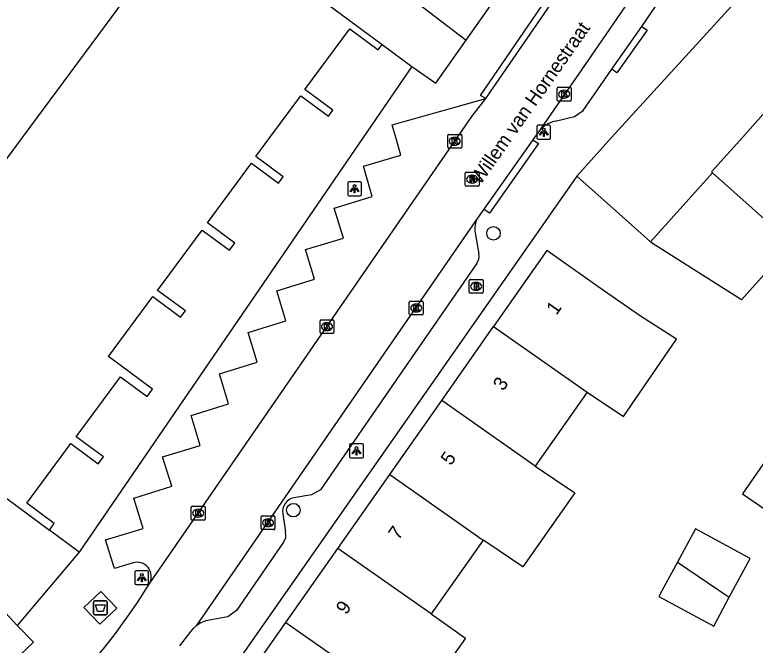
# Model space of a CAD drawing. Extents: x 161801 to 162379, y 382315 to 382832.
# Drawn here: x 161941.1 to 161994.6, y 382713.3 to 382758.9 of the extents above; entities that cross this region are included whole.
import ezdxf

# ---------------------------------------------------------------- set-up
doc = ezdxf.new("R2010")
doc.units = 0
for name, color, linetype in [('IMGEO_Afval_apart_plaats', 7, 'Continuous'), ('IMGEO_Boom', 7, 'Continuous'), ('IMGEO_Brandkraan', 7, 'Continuous'), ('IMGEO_Kolk', 7, 'Continuous'), ('IMGEO_Lichtpunt', 7, 'Continuous'), ('IMGEO_Openbare_ruimte_label', 7, 'Continuous'), ('IMGEO_Pand', 7, 'Continuous'), ('IMGEO_Pand_nummerreeks', 7, 'Continuous'), ('IMGEO_Parkeervlak_open', 7, 'Continuous'), ('IMGEO_Rijbaan_lokaal_open', 7, 'Continuous'), ('IMGEO_Rioolput', 7, 'Continuous'), ('IMGEO_Voetpad_gesloten', 7, 'Continuous'), ('IMGEO_Voetpad_open', 7, 'Continuous')]:
    doc.layers.add(name, color=color, linetype=linetype)

msp = doc.modelspace()

# ---------------------------------------------------------------- linework, layer by layer
at = {"layer": 'IMGEO_Afval_apart_plaats'}
for p, q in [((161946.804, 382715.605), (161946.804, 382716.405)), ((161946.804, 382716.405), (161946.804, 382715.605)), ((161946.904, 382716.505), (161947.694, 382716.505)), ((161947.694, 382716.505), (161946.904, 382716.505)), ((161947.794, 382716.405), (161947.794, 382715.605)), ((161947.794, 382715.605), (161947.794, 382716.405)), ((161947.694, 382715.505), (161946.904, 382715.505)), ((161946.904, 382715.505), (161947.694, 382715.505))]:
    msp.add_line(p, q, dxfattribs=at)
msp.add_lwpolyline([(161946.947, 382716.219), (161947.651, 382716.219), (161947.502, 382715.749), (161947.096, 382715.749), (161946.947, 382716.219)], dxfattribs=at)
for centre, start, end in [((161946.904, 382716.405), 90, 180), ((161946.904, 382716.405), 90, 180), ((161947.694, 382716.405), 0, 90), ((161947.694, 382716.405), 360, 90), ((161946.904, 382715.605), 180, 270), ((161946.904, 382715.605), 180, 270), ((161947.694, 382715.605), 270, 0), ((161947.694, 382715.605), 270, 0)]:
    msp.add_arc(centre, 0.1, start, end, dxfattribs=at)
at = {"layer": 'IMGEO_Boom'}
for centre in [(161975.717, 382743.07), (161961.254, 382723.06)]:
    msp.add_circle(centre, 0.489, dxfattribs=at)
at = {"layer": 'IMGEO_Brandkraan'}
for p, q in [((161973.966, 382738.812), (161973.966, 382739.664)), ((161974.041, 382739.738), (161974.893, 382739.738)), ((161974.454, 382739.518), (161974.479, 382739.518)), ((161974.967, 382739.664), (161974.967, 382738.812)), ((161974.477, 382738.958), (161974.452, 382738.958)), ((161974.893, 382738.738), (161974.041, 382738.738))]:
    msp.add_line(p, q, dxfattribs=at)
for points in [[(161973.966, 382738.812), (161973.966, 382739.664)], [(161974.041, 382739.738), (161974.893, 382739.738)], [(161974.314, 382739.438), (161974.314, 382739.038), (161974.527, 382739.038)], [(161974.545, 382739.438), (161974.314, 382739.438)], [(161974.493, 382739.357), (161974.439, 382739.357), (161974.439, 382739.281)], [(161974.967, 382739.664), (161974.967, 382738.812)], [(161974.439, 382739.281), (161974.492, 382739.281)], [(161974.501, 382739.205), (161974.439, 382739.205), (161974.439, 382739.124)], [(161974.439, 382739.124), (161974.501, 382739.124)], [(161974.893, 382738.738), (161974.041, 382738.738)]]:
    msp.add_lwpolyline(points, dxfattribs=at)
for centre, radius, start, end in [((161974.043, 382739.662), 0.0765, 91.552, 178.448), ((161974.043, 382739.662), 0.0765, 91.552, 178.448), ((161974.494, 382739.319), 0.0379, 267.8285, 90.9355), ((161974.549, 382739.293), 0.145, 59.4692, 91.5367), ((161974.574, 382739.34), 0.0922, 285.5137, 58.1501), ((161974.891, 382739.662), 0.0765, 1.552, 88.448), ((161974.891, 382739.662), 0.0765, 1.552, 88.448), ((161974.043, 382738.814), 0.0765, 181.552, 268.448), ((161974.043, 382738.814), 0.0765, 181.552, 268.448), ((161974.502, 382739.164), 0.0404, 269.8759, 90.5077), ((161974.533, 382739.289), 0.251, 268.6676, 293.5347), ((161974.579, 382739.148), 0.105, 301.3115, 78.989), ((161974.891, 382738.814), 0.0765, 271.552, 358.448), ((161974.891, 382738.814), 0.0765, 271.552, 358.448)]:
    msp.add_arc(centre, radius, start, end, dxfattribs=at)
for centre, major_axis, ratio, start_param, end_param in [((161974.453, 382739.238), (-0.387, 0.002), 0.722429, 4.712389, 7.853982), ((161974.478, 382739.238), (-0.39, 0.002), 0.717154, 1.570796, 4.712389)]:
    msp.add_ellipse(centre, major_axis=major_axis, ratio=ratio, start_param=start_param, end_param=end_param, dxfattribs=at)
at = {"layer": 'IMGEO_Kolk'}
for p, q in [((161980.328, 382752.702), (161980.328, 382753.554)), ((161980.403, 382753.628), (161981.255, 382753.628)), ((161980.816, 382753.408), (161980.841, 382753.408)), ((161981.329, 382753.554), (161981.329, 382752.702)), ((161980.839, 382752.848), (161980.814, 382752.848)), ((161981.255, 382752.628), (161980.403, 382752.628)), ((161972.421, 382749.297), (161972.421, 382750.149)), ((161972.496, 382750.223), (161973.348, 382750.223)), ((161973.422, 382750.149), (161973.422, 382749.297)), ((161972.909, 382750.003), (161972.934, 382750.003)), ((161973.348, 382749.223), (161972.496, 382749.223)), ((161972.932, 382749.443), (161972.907, 382749.443)), ((161969.634, 382737.246), (161969.634, 382738.098)), ((161969.709, 382738.172), (161970.561, 382738.172)), ((161970.122, 382737.952), (161970.147, 382737.952)), ((161970.635, 382738.098), (161970.635, 382737.246)), ((161970.145, 382737.392), (161970.12, 382737.392)), ((161963.184, 382735.901), (161963.184, 382736.753)), ((161963.259, 382736.827), (161964.111, 382736.827)), ((161964.185, 382736.753), (161964.185, 382735.901)), ((161970.561, 382737.172), (161969.709, 382737.172)), ((161963.672, 382736.607), (161963.697, 382736.607)), ((161964.111, 382735.827), (161963.259, 382735.827)), ((161963.695, 382736.047), (161963.67, 382736.047)), ((161953.948, 382723.346), (161954.8, 382723.346)), ((161953.873, 382722.42), (161953.873, 382723.272)), ((161954.361, 382723.126), (161954.386, 382723.126)), ((161954.874, 382723.272), (161954.874, 382722.42)), ((161954.8, 382722.346), (161953.948, 382722.346)), ((161954.384, 382722.566), (161954.359, 382722.566)), ((161958.924, 382721.728), (161958.924, 382722.58)), ((161958.999, 382722.654), (161959.851, 382722.654)), ((161959.412, 382722.434), (161959.437, 382722.434)), ((161959.925, 382722.58), (161959.925, 382721.728)), ((161959.435, 382721.874), (161959.41, 382721.874)), ((161959.851, 382721.654), (161958.999, 382721.654))]:
    msp.add_line(p, q, dxfattribs=at)
for points in [[(161980.328, 382752.702), (161980.328, 382753.554)], [(161980.403, 382753.628), (161981.255, 382753.628)], [(161980.649, 382753.328), (161980.772, 382753.328), (161980.772, 382753.177), (161980.902, 382753.328), (161981.066, 382753.328), (161980.92, 382753.177), (161981.073, 382752.928), (161980.921, 382752.928), (161980.836, 382753.092), (161980.772, 382753.025), (161980.772, 382752.928), (161980.649, 382752.928), (161980.649, 382753.328)], [(161981.329, 382753.554), (161981.329, 382752.702)], [(161981.255, 382752.628), (161980.403, 382752.628)], [(161972.421, 382749.297), (161972.421, 382750.149)], [(161972.496, 382750.223), (161973.348, 382750.223)], [(161973.422, 382750.149), (161973.422, 382749.297)], [(161972.742, 382749.923), (161972.865, 382749.923), (161972.865, 382749.772), (161972.995, 382749.923), (161973.159, 382749.923), (161973.013, 382749.772), (161973.166, 382749.523), (161973.014, 382749.523), (161972.929, 382749.687), (161972.865, 382749.62), (161972.865, 382749.523), (161972.742, 382749.523), (161972.742, 382749.923)], [(161973.348, 382749.223), (161972.496, 382749.223)], [(161969.634, 382737.246), (161969.634, 382738.098)], [(161969.709, 382738.172), (161970.561, 382738.172)], [(161969.955, 382737.872), (161970.078, 382737.872), (161970.078, 382737.721), (161970.208, 382737.872), (161970.372, 382737.872), (161970.226, 382737.721), (161970.379, 382737.472), (161970.227, 382737.472), (161970.142, 382737.636), (161970.078, 382737.569), (161970.078, 382737.472), (161969.955, 382737.472), (161969.955, 382737.872)], [(161970.635, 382738.098), (161970.635, 382737.246)], [(161963.184, 382735.901), (161963.184, 382736.753)], [(161963.259, 382736.827), (161964.111, 382736.827)], [(161964.185, 382736.753), (161964.185, 382735.901)], [(161970.561, 382737.172), (161969.709, 382737.172)], [(161963.505, 382736.527), (161963.628, 382736.527), (161963.628, 382736.376), (161963.758, 382736.527), (161963.922, 382736.527), (161963.776, 382736.376), (161963.929, 382736.127), (161963.777, 382736.127), (161963.692, 382736.291), (161963.628, 382736.224), (161963.628, 382736.127), (161963.505, 382736.127), (161963.505, 382736.527)], [(161964.111, 382735.827), (161963.259, 382735.827)], [(161953.948, 382723.346), (161954.8, 382723.346)], [(161953.873, 382722.42), (161953.873, 382723.272)], [(161954.194, 382723.046), (161954.317, 382723.046), (161954.317, 382722.895), (161954.447, 382723.046), (161954.611, 382723.046), (161954.465, 382722.895), (161954.618, 382722.646), (161954.466, 382722.646), (161954.381, 382722.81), (161954.317, 382722.743), (161954.317, 382722.646), (161954.194, 382722.646), (161954.194, 382723.046)], [(161954.874, 382723.272), (161954.874, 382722.42)], [(161954.8, 382722.346), (161953.948, 382722.346)], [(161958.924, 382721.728), (161958.924, 382722.58)], [(161958.999, 382722.654), (161959.851, 382722.654)], [(161959.245, 382722.354), (161959.368, 382722.354), (161959.368, 382722.203), (161959.498, 382722.354), (161959.662, 382722.354), (161959.516, 382722.203), (161959.669, 382721.954), (161959.517, 382721.954), (161959.432, 382722.118), (161959.368, 382722.051), (161959.368, 382721.954), (161959.245, 382721.954), (161959.245, 382722.354)], [(161959.925, 382722.58), (161959.925, 382721.728)], [(161959.851, 382721.654), (161958.999, 382721.654)]]:
    msp.add_lwpolyline(points, dxfattribs=at)
for centre, start, end in [((161980.405, 382753.552), 91.552, 178.448), ((161980.405, 382753.552), 91.552, 178.448), ((161981.253, 382753.552), 1.552, 88.448), ((161981.253, 382753.552), 1.552, 88.448), ((161980.405, 382752.704), 181.552, 268.448), ((161980.405, 382752.704), 181.552, 268.448), ((161981.253, 382752.704), 271.552, 358.448), ((161981.253, 382752.704), 271.552, 358.448), ((161972.498, 382750.147), 91.552, 178.448), ((161972.498, 382750.147), 91.552, 178.448), ((161973.346, 382750.147), 1.552, 88.448), ((161973.346, 382750.147), 1.552, 88.448), ((161972.498, 382749.299), 181.552, 268.448), ((161972.498, 382749.299), 181.552, 268.448), ((161973.346, 382749.299), 271.552, 358.448), ((161973.346, 382749.299), 271.552, 358.448), ((161969.711, 382738.096), 91.552, 178.448), ((161969.711, 382738.096), 91.552, 178.448), ((161970.559, 382738.096), 1.552, 88.448), ((161970.559, 382738.096), 1.552, 88.448), ((161969.711, 382737.248), 181.552, 268.448), ((161969.711, 382737.248), 181.552, 268.448), ((161970.559, 382737.248), 271.552, 358.448), ((161970.559, 382737.248), 271.552, 358.448), ((161963.261, 382736.751), 91.552, 178.448), ((161963.261, 382736.751), 91.552, 178.448), ((161964.109, 382736.751), 1.552, 88.448), ((161964.109, 382736.751), 1.552, 88.448), ((161963.261, 382735.903), 181.552, 268.448), ((161963.261, 382735.903), 181.552, 268.448), ((161964.109, 382735.903), 271.552, 358.448), ((161964.109, 382735.903), 271.552, 358.448), ((161953.95, 382723.27), 91.552, 178.448), ((161953.95, 382723.27), 91.552, 178.448), ((161954.798, 382723.27), 1.552, 88.448), ((161954.798, 382723.27), 1.552, 88.448), ((161953.95, 382722.422), 181.552, 268.448), ((161953.95, 382722.422), 181.552, 268.448), ((161954.798, 382722.422), 271.552, 358.448), ((161954.798, 382722.422), 271.552, 358.448), ((161959.001, 382722.578), 91.552, 178.448), ((161959.001, 382722.578), 91.552, 178.448), ((161959.849, 382722.578), 1.552, 88.448), ((161959.849, 382722.578), 1.552, 88.448), ((161959.001, 382721.73), 181.552, 268.448), ((161959.001, 382721.73), 181.552, 268.448), ((161959.849, 382721.73), 271.552, 358.448), ((161959.849, 382721.73), 271.552, 358.448)]:
    msp.add_arc(centre, 0.0765, start, end, dxfattribs=at)
for centre, major_axis, ratio, start_param, end_param in [((161980.815, 382753.128), (-0.387, 0.002), 0.722429, 4.712389, 7.853982), ((161980.84, 382753.128), (-0.39, 0.002), 0.717154, 1.570796, 4.712389), ((161972.908, 382749.723), (-0.387, 0.002), 0.722429, 4.712389, 7.853982), ((161972.933, 382749.723), (-0.39, 0.002), 0.717154, 1.570796, 4.712389), ((161970.121, 382737.672), (-0.387, 0.002), 0.722429, 4.712389, 7.853982), ((161970.146, 382737.672), (-0.39, 0.002), 0.717154, 1.570796, 4.712389), ((161963.671, 382736.327), (-0.387, 0.002), 0.722429, 4.712389, 7.853982), ((161963.696, 382736.327), (-0.39, 0.002), 0.717154, 1.570796, 4.712389), ((161954.36, 382722.846), (-0.387, 0.002), 0.722429, 4.712389, 7.853982), ((161954.385, 382722.846), (-0.39, 0.002), 0.717154, 1.570796, 4.712389), ((161959.411, 382722.154), (-0.387, 0.002), 0.722429, 4.712389, 7.853982), ((161959.436, 382722.154), (-0.39, 0.002), 0.717154, 1.570796, 4.712389)]:
    msp.add_ellipse(centre, major_axis=major_axis, ratio=ratio, start_param=start_param, end_param=end_param, dxfattribs=at)
at = {"layer": 'IMGEO_Lichtpunt'}
for p, q in [((161978.856, 382750.781), (161978.856, 382749.974)), ((161978.856, 382750.781), (161978.856, 382749.974)), ((161979.758, 382750.876), (161978.95, 382750.876)), ((161979.758, 382750.876), (161978.95, 382750.876)), ((161979.852, 382749.974), (161979.852, 382750.781)), ((161979.852, 382749.974), (161979.852, 382750.781)), ((161978.95, 382749.88), (161979.758, 382749.88)), ((161978.95, 382749.88), (161979.758, 382749.88)), ((161965.183, 382746.692), (161965.183, 382745.885)), ((161965.183, 382746.692), (161965.183, 382745.885)), ((161966.085, 382746.787), (161965.277, 382746.787)), ((161966.085, 382746.787), (161965.277, 382746.787)), ((161966.179, 382745.885), (161966.179, 382746.692)), ((161966.179, 382745.885), (161966.179, 382746.692)), ((161965.277, 382745.791), (161966.085, 382745.791)), ((161965.277, 382745.791), (161966.085, 382745.791)), ((161965.319, 382727.755), (161965.319, 382726.948)), ((161965.319, 382727.755), (161965.319, 382726.948)), ((161966.221, 382727.85), (161965.413, 382727.85)), ((161966.221, 382727.85), (161965.413, 382727.85)), ((161966.315, 382726.948), (161966.315, 382727.755)), ((161966.315, 382726.948), (161966.315, 382727.755)), ((161965.413, 382726.854), (161966.221, 382726.854)), ((161965.413, 382726.854), (161966.221, 382726.854)), ((161949.794, 382718.592), (161949.794, 382717.785)), ((161949.794, 382718.592), (161949.794, 382717.785)), ((161950.696, 382718.687), (161949.888, 382718.687)), ((161950.696, 382718.687), (161949.888, 382718.687)), ((161950.79, 382717.785), (161950.79, 382718.592)), ((161950.79, 382717.785), (161950.79, 382718.592)), ((161949.888, 382717.691), (161950.696, 382717.691)), ((161949.888, 382717.691), (161950.696, 382717.691))]:
    msp.add_line(p, q, dxfattribs=at)
for points in [[(161979.23, 382750.445), (161979.269, 382750.417), (161979.081, 382750.155), (161979.043, 382750.182), (161979.23, 382750.445)], [(161979.332, 382750.397), (161979.379, 382750.397), (161979.379, 382750.075), (161979.332, 382750.075), (161979.332, 382750.397)], [(161979.442, 382750.417), (161979.48, 382750.444), (161979.667, 382750.182), (161979.628, 382750.154), (161979.442, 382750.417)], [(161965.557, 382746.356), (161965.596, 382746.328), (161965.408, 382746.066), (161965.37, 382746.093), (161965.557, 382746.356)], [(161965.659, 382746.308), (161965.706, 382746.308), (161965.706, 382745.986), (161965.659, 382745.986), (161965.659, 382746.308)], [(161965.769, 382746.328), (161965.807, 382746.355), (161965.994, 382746.093), (161965.955, 382746.065), (161965.769, 382746.328)], [(161965.693, 382727.419), (161965.732, 382727.391), (161965.544, 382727.129), (161965.506, 382727.156), (161965.693, 382727.419)], [(161965.795, 382727.371), (161965.842, 382727.371), (161965.842, 382727.049), (161965.795, 382727.049), (161965.795, 382727.371)], [(161965.905, 382727.391), (161965.943, 382727.418), (161966.13, 382727.156), (161966.091, 382727.128), (161965.905, 382727.391)], [(161950.168, 382718.256), (161950.207, 382718.228), (161950.019, 382717.966), (161949.981, 382717.993), (161950.168, 382718.256)], [(161950.27, 382718.208), (161950.317, 382718.208), (161950.317, 382717.886), (161950.27, 382717.886), (161950.27, 382718.208)], [(161950.38, 382718.228), (161950.418, 382718.255), (161950.605, 382717.993), (161950.566, 382717.965), (161950.38, 382718.228)]]:
    msp.add_lwpolyline(points, dxfattribs=at)
for centre in [(161979.355, 382750.579), (161965.682, 382746.49), (161965.818, 382727.553), (161950.293, 382718.39)]:
    msp.add_circle(centre, 0.0994, dxfattribs=at)
for centre, start, end in [((161978.95, 382750.781), 90, 180), ((161978.95, 382750.781), 90, 180), ((161979.758, 382750.781), 0, 90), ((161979.758, 382750.781), 0, 90), ((161978.95, 382749.974), 180, 270), ((161978.95, 382749.974), 180, 270), ((161979.758, 382749.974), 270, 0), ((161979.758, 382749.974), 270, 360), ((161965.277, 382746.692), 90, 180), ((161965.277, 382746.692), 90, 180), ((161966.085, 382746.692), 0, 90), ((161966.085, 382746.692), 0, 90), ((161965.277, 382745.885), 180, 270), ((161965.277, 382745.885), 180, 270), ((161966.085, 382745.885), 270, 0), ((161966.085, 382745.885), 270, 360), ((161965.413, 382727.755), 90, 180), ((161965.413, 382727.755), 90, 180), ((161966.221, 382727.755), 0, 90), ((161966.221, 382727.755), 0, 90), ((161965.413, 382726.948), 180, 270), ((161965.413, 382726.948), 180, 270), ((161966.221, 382726.948), 270, 0), ((161966.221, 382726.948), 270, 360), ((161949.888, 382718.592), 90, 180), ((161949.888, 382718.592), 90, 180), ((161950.696, 382718.592), 0, 90), ((161950.696, 382718.592), 0, 90), ((161949.888, 382717.785), 180, 270), ((161949.888, 382717.785), 180, 270), ((161950.696, 382717.785), 270, 0), ((161950.696, 382717.785), 270, 360)]:
    msp.add_arc(centre, 0.0946, start, end, dxfattribs=at)
at = {"layer": 'IMGEO_Pand'}
for points in [[(161973.752, 382757.022), (161980.996, 382767.347)], [(161929.946, 382734.127), (161941.685, 382750), (161954.083, 382766.765), (161967.663, 382756.723)], [(161997.519, 382764.558), (161984.249, 382750), (161981.747, 382747.198)], [(161968.421, 382761.136), (161969.677, 382760.169), (161973.752, 382757.022)], [(161943.621, 382721.62), (161943.969, 382722.091), (161941.982, 382723.561), (161945.17, 382727.873), (161947.145, 382726.412), (161947.523, 382726.923), (161945.564, 382728.372), (161948.762, 382732.697), (161950.683, 382731.277), (161951.074, 382731.807), (161947.883, 382734.166), (161951.084, 382738.495), (161953.105, 382737.001), (161953.445, 382737.46), (161951.434, 382738.947), (161954.66, 382743.309), (161956.641, 382741.844), (161957.021, 382742.359), (161955.042, 382743.822), (161958.233, 382748.137), (161960.189, 382746.69), (161960.524, 382747.144), (161958.536, 382748.615), (161959.56, 382750), (161961.787, 382753.011), (161963.782, 382751.536), (161964.103, 382751.97), (161962.085, 382753.462), (161965.327, 382757.846), (161967.374, 382756.333), (161967.663, 382756.723)], [(161991.557, 382747.445), (161991.488, 382747.507), (161993.712, 382750), (161995.75, 382752.284), (161995.84, 382752.203)], [(161987.064, 382742.454), (161991.557, 382747.445)], [(161991.557, 382747.445), (161997.283, 382742.337), (161993.653, 382738.267), (161987.136, 382742.39), (161987.064, 382742.454)], [(161981.747, 382747.198), (161985.478, 382743.87), (161987.064, 382742.454)], [(161982.489, 382731.601), (161985.112, 382729.835), (161988.941, 382735.417), (161986.339, 382737.072), (161983.664, 382738.949), (161979.571, 382741.821), (161975.729, 382736.346)], [(161971.974, 382730.996), (161975.729, 382736.346)], [(161975.729, 382736.346), (161982.489, 382731.601)], [(161982.489, 382731.601), (161978.728, 382726.255)], [(161968.22, 382725.647), (161971.974, 382730.996)], [(161978.728, 382726.255), (161971.974, 382730.996)], [(161998.854, 382724.777), (161995.616, 382727.001), (161993.72, 382724.242), (161996.958, 382722.018), (161998.854, 382724.777)], [(161978.728, 382726.255), (161981.603, 382724.304), (161977.848, 382718.967), (161975.308, 382720.671), (161974.962, 382720.903)], [(161964.465, 382720.297), (161968.22, 382725.647)], [(161968.22, 382725.647), (161974.962, 382720.903)], [(161939.486, 382723.371), (161939.284, 382723.823), (161939.764, 382724.472), (161943.621, 382721.62)], [(161992.761, 382716.766), (161994.281, 382719.576), (161990.323, 382721.718), (161989.014, 382719.297)], [(161974.962, 382720.903), (161971.206, 382715.565)], [(161960.71, 382714.946), (161964.465, 382720.297)], [(161971.206, 382715.565), (161964.465, 382720.297)], [(161989.014, 382719.297), (161987.749, 382716.961), (161987.679, 382716.831), (161991.388, 382714.824), (161991.568, 382714.727), (161991.637, 382714.69), (161992.761, 382716.766)], [(161989.014, 382719.297), (161992.761, 382716.766)], [(161971.206, 382715.565), (161973.691, 382713.821), (161971.373, 382710.526), (161968.888, 382712.27), (161967.445, 382710.219)], [(161956.87, 382709.475), (161960.71, 382714.946)], [(161960.71, 382714.946), (161967.445, 382710.219)]]:
    msp.add_lwpolyline(points, dxfattribs=at)
at = {"layer": 'IMGEO_Parkeervlak_open'}
msp.add_lwpolyline([(161967.663, 382756.723), (161969.821, 382755.127)], dxfattribs=at)
at = {"layer": 'IMGEO_Rijbaan_lokaal_open'}
for points in [[(161991.783, 382769.02), (161982.788, 382755.905), (161978.946, 382750.365)], [(161975.168, 382752.813), (161979.867, 382759.641)], [(161950.871, 382717.792), (161974.155, 382751.509), (161975.168, 382752.813)], [(161978.946, 382750.365), (161978.687, 382750), (161978.57, 382749.833)], [(161978.57, 382749.833), (161975.012, 382744.815)], [(161975.012, 382744.815), (161974.497, 382744.072)], [(161974.497, 382744.072), (161954.232, 382714.711)], [(161954.232, 382714.711), (161954.011, 382714.515), (161953.841, 382714.33), (161953.014, 382713.254)]]:
    msp.add_lwpolyline(points, dxfattribs=at)
msp.add_arc((161913.61, 382740.517), 43.644, 316.3953, 328.6224, dxfattribs=at)
at = {"layer": 'IMGEO_Rioolput'}
for p, q in [((161973.677, 382746.556), (161973.677, 382747.408)), ((161973.752, 382747.482), (161974.604, 382747.482)), ((161974.678, 382747.408), (161974.678, 382746.556)), ((161974.165, 382747.262), (161974.19, 382747.262)), ((161974.604, 382746.482), (161973.752, 382746.482)), ((161974.188, 382746.702), (161974.163, 382746.702))]:
    msp.add_line(p, q, dxfattribs=at)
for points in [[(161973.677, 382746.556), (161973.677, 382747.408)], [(161973.752, 382747.482), (161974.604, 382747.482)], [(161974.678, 382747.408), (161974.678, 382746.556)], [(161974.266, 382747.18), (161974.014, 382747.182), (161974.014, 382746.782)], [(161974.014, 382746.782), (161974.138, 382746.782), (161974.138, 382746.944), (161974.149, 382746.944)], [(161974.192, 382747.101), (161974.138, 382747.101), (161974.138, 382747.02)], [(161974.138, 382747.02), (161974.19, 382747.02)], [(161974.196, 382746.915), (161974.267, 382746.782), (161974.407, 382746.782), (161974.342, 382746.908)], [(161974.604, 382746.482), (161973.752, 382746.482)]]:
    msp.add_lwpolyline(points, dxfattribs=at)
for centre, radius, start, end in [((161973.754, 382747.406), 0.0765, 91.552, 178.448), ((161973.754, 382747.406), 0.0765, 91.552, 178.448), ((161974.602, 382747.406), 0.0765, 1.552, 88.448), ((161974.602, 382747.406), 0.0765, 1.552, 88.448), ((161974.148, 382746.891), 0.0533, 26.0293, 88.6989), ((161974.174, 382747.209), 0.19, 274.7715, 282.9687), ((161974.198, 382747.005), 0.0964, 77.0061, 93.1865), ((161974.212, 382747.062), 0.0378, 276.6634, 79.6772), ((161974.265, 382747.07), 0.109, 350.3612, 89.416), ((161974.263, 382747.07), 0.112, 277.5842, 350.9817), ((161974.247, 382746.855), 0.108, 29.5134, 73.7905), ((161973.754, 382746.558), 0.0765, 181.552, 268.448), ((161973.754, 382746.558), 0.0765, 181.552, 268.448), ((161974.602, 382746.558), 0.0765, 271.552, 358.448), ((161974.602, 382746.558), 0.0765, 271.552, 358.448)]:
    msp.add_arc(centre, radius, start, end, dxfattribs=at)
for centre, major_axis, ratio, start_param, end_param in [((161974.164, 382746.982), (-0.387, 0.002), 0.722429, 4.712389, 7.853982), ((161974.189, 382746.982), (-0.39, 0.002), 0.717154, 1.570796, 4.712389)]:
    msp.add_ellipse(centre, major_axis=major_axis, ratio=ratio, start_param=start_param, end_param=end_param, dxfattribs=at)
at = {"layer": 'IMGEO_Voetpad_gesloten'}
msp.add_lwpolyline([(161947.342, 382717.189), (161948.483, 382715.983), (161947.255, 382714.821), (161946.114, 382716.027), (161947.342, 382717.189)], dxfattribs=at)
at = {"layer": 'IMGEO_Voetpad_open'}
for points in [[(161986.435, 382758.019), (161991.536, 382765.487)], [(161975.168, 382752.813), (161974.785, 382753.021), (161979.484, 382759.903), (161979.867, 382759.641)], [(161984.273, 382754.939), (161986.435, 382758.019)], [(161986.435, 382758.019), (161986.82, 382757.755), (161984.633, 382754.664), (161984.273, 382754.939)], [(161969.821, 382755.127), (161971.541, 382753.922), (161973.752, 382757.022)], [(161969.821, 382755.127), (161966.31, 382750), (161945.78, 382720.02)], [(161980.179, 382751.181), (161981.574, 382751.502), (161982.208, 382751.95), (161984.273, 382754.939)], [(161949.671, 382719.261), (161948.329, 382718.853), (161947.662, 382720.928), (161950.399, 382721.747), (161949.723, 382723.934), (161952.468, 382724.788), (161951.794, 382726.921), (161954.513, 382727.726), (161953.867, 382729.894), (161956.565, 382730.741), (161955.922, 382732.912), (161958.647, 382733.757), (161957.979, 382735.907), (161960.71, 382736.757), (161960.061, 382738.905), (161962.784, 382739.751), (161962.14, 382741.911), (161964.866, 382742.715), (161964.207, 382744.9), (161966.947, 382745.726), (161966.314, 382747.929), (161969.029, 382748.71), (161968.649, 382750), (161968.392, 382750.903), (161975.168, 382752.813)], [(161978.57, 382749.833), (161978.963, 382749.556), (161975.424, 382744.525), (161975.012, 382744.815)], [(161981.747, 382747.198), (161955.826, 382710.123)], [(161974.422, 382742.957), (161974.67, 382741.595)], [(161974.494, 382740.858), (161968.922, 382732.829), (161963.223, 382724.527), (161962.572, 382724.162), (161961.29, 382723.965)], [(161960.49, 382722.799), (161960.696, 382721.466)], [(161945.78, 382720.02), (161943.621, 382721.62)], [(161960.54, 382720.752), (161957.145, 382715.801), (161956.513, 382715.352), (161955.188, 382715.124)], [(161945.78, 382720.02), (161941.286, 382714.73)], [(161941.286, 382714.73), (161939.315, 382716.857)], [(161941.286, 382714.73), (161942.474, 382713.523), (161925.083, 382696.984)]]:
    msp.add_lwpolyline(points, dxfattribs=at)
for centre, radius, start, end in [((161980.61, 382749.191), 2.036, 102.2066, 144.7866), ((161976.279, 382743.392), 1.907, 159.117, 193.1867), ((161973.646, 382741.45), 1.034, 325.0722, 8.0657), ((161961.492, 382722.969), 1.016, 101.463, 189.6284), ((161959.863, 382721.274), 0.855, 322.3806, 12.97), ((161949.95, 382718.265), 1.035, 332.8283, 105.6612), ((161955.555, 382712.961), 2.193, 99.6324, 127.0971)]:
    msp.add_arc(centre, radius, start, end, dxfattribs=at)

# ---------------------------------------------------------------- texts
at = {"layer": 'IMGEO_Openbare_ruimte_label'}
msp.add_text('Willem van Hornestraat', height=1, rotation=54.9751, dxfattribs=at).set_placement((161974.775, 382746.524))
at = {"layer": 'IMGEO_Pand_nummerreeks'}
for s, rotation, p in [('1', 54.9409, (161980.272, 382737.11)), ('3', 54.9381, (161976.422, 382731.625)), ('5', 54.9381, (161972.639, 382726.234)), ('7', 54.9381, (161968.855, 382720.843)), ('9', 54.9409, (161965.072, 382715.453))]:
    msp.add_text(s, height=1, rotation=rotation, dxfattribs=at).set_placement(p)

doc.saveas('drawing.dxf')
